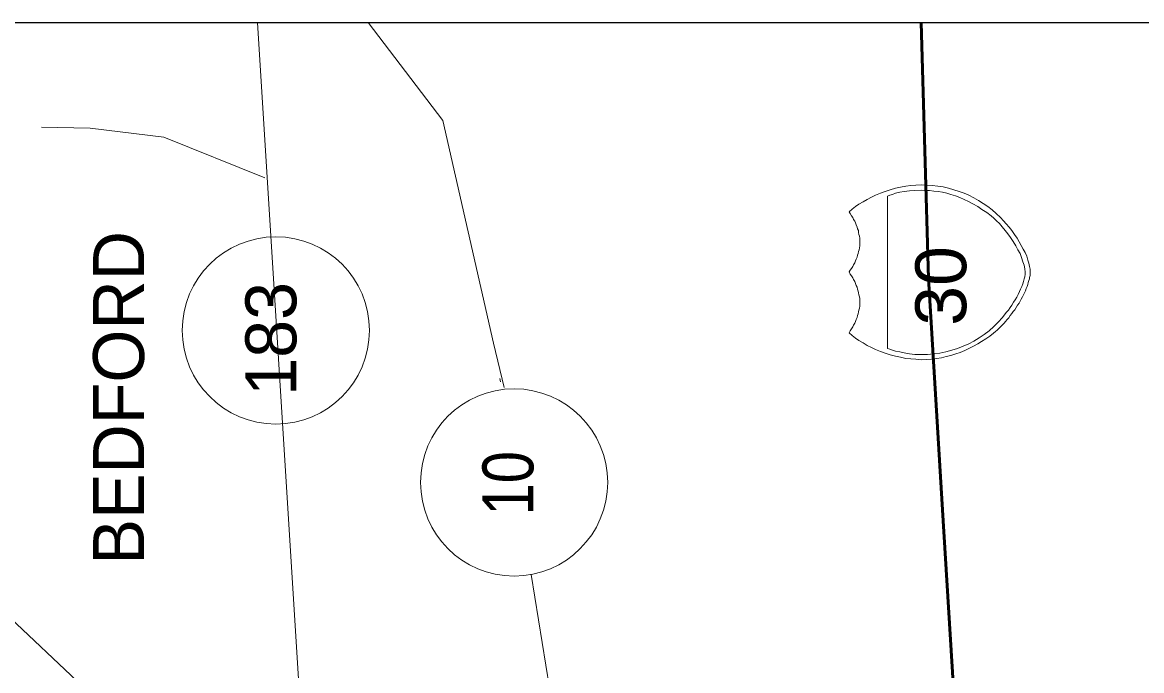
# Model space of a CAD drawing. Extents: x 2363323 to 2367082, y 6956018 to 6980837.
# Drawn here: x 2365426.8 to 2365762.8, y 6956343.7 to 6956538.2 of the extents above; entities that cross this region are included whole.
import ezdxf

# ---------------------------------------------------------------- set-up
doc = ezdxf.new("R2010")
doc.units = 0
doc.header["$LTSCALE"] = 4.1
for name, color, linetype, lineweight in [('61', 7, 'Continuous', 40), ('62', 7, 'Continuous', 13), ('63', 7, 'Continuous', 13)]:
    doc.layers.add(name, color=color, linetype=linetype, lineweight=lineweight)

msp = doc.modelspace()

# ---------------------------------------------------------------- linework, layer by layer
at = {"layer": '61', "lineweight": 25}
msp.add_lwpolyline([(2365293.134, 6956018.485), (2365293.134, 6956538.196), (2365958.89, 6956538.196), (2365958.89, 6956018.485)], close=True, dxfattribs=at)
at = {"layer": '62'}
for p, q in [((2365527.469, 6956056.34), (2365497.377, 6956538.196)), ((2365552.969, 6956508.784), (2365530.565, 6956538.196)), ((2365447.113, 6956506.444), (2365432.529, 6956506.716)), ((2365568.178, 6956441.987), (2365571.408, 6956428.587)), ((2365446.841, 6956337.136), (2365409.581, 6956372.152)), ((2365585.001, 6956338.484), (2365579.55, 6956372.48))]:
    msp.add_line(p, q, dxfattribs=at)
at = {"layer": '62', "lineweight": 53}
msp.add_line((2365708.857, 6956297.252), (2365703.273, 6956388.628), dxfattribs=at)
msp.add_lwpolyline([(2365696.665, 6956538.196), (2365698.781, 6956461.356), (2365703.273, 6956388.628)], dxfattribs=at)
at = {"layer": '62'}
for points in [[(2365499.593, 6956491.596), (2365469.265, 6956503.744), (2365447.113, 6956506.444)], [(2365676.336, 6956465.449), (2365676.675, 6956466.055), (2365676.945, 6956466.601), (2365677.149, 6956467.135), (2365677.416, 6956467.747), (2365677.485, 6956468.356), (2365677.755, 6956468.824), (2365677.827, 6956469.436), (2365677.959, 6956469.973), (2365678.091, 6956470.579), (2365678.157, 6956471.125), (2365678.157, 6956471.731), (2365678.157, 6956472.337), (2365678.157, 6956472.877), (2365678.157, 6956473.417), (2365678.091, 6956474.023), (2365677.956, 6956474.566), (2365677.827, 6956475.109), (2365677.758, 6956475.715), (2365677.488, 6956476.255), (2365677.419, 6956476.795), (2365677.146, 6956477.401), (2365676.945, 6956478.007), (2365676.675, 6956478.553), (2365676.339, 6956479.087), (2365676.069, 6956479.627), (2365675.727, 6956480.167), (2365675.319, 6956480.845), (2365674.986, 6956481.379), (2365675.868, 6956482.126), (2365676.876, 6956482.939), (2365677.953, 6956483.677), (2365679.171, 6956484.355), (2365680.386, 6956485.027), (2365681.673, 6956485.771), (2365682.951, 6956486.377), (2365684.373, 6956486.986), (2365685.855, 6956487.463), (2365687.337, 6956487.931), (2365688.891, 6956488.405), (2365690.448, 6956488.741), (2365691.999, 6956489.017), (2365693.487, 6956489.209), (2365695.035, 6956489.353), (2365696.586, 6956489.419), (2365698.275, 6956489.347), (2365699.967, 6956489.215), (2365701.647, 6956489.017), (2365703.201, 6956488.807), (2365704.821, 6956488.471), (2365706.447, 6956487.931), (2365707.995, 6956487.457), (2365709.549, 6956486.986), (2365710.965, 6956486.311), (2365712.447, 6956485.507), (2365713.866, 6956484.757), (2365715.219, 6956483.881), (2365716.635, 6956482.936), (2365717.916, 6956481.925), (2365719.131, 6956480.845), (2365720.415, 6956479.627), (2365721.297, 6956478.685), (2365722.167, 6956477.737), (2365723.049, 6956476.726), (2365723.859, 6956475.715), (2365724.597, 6956474.566), (2365725.407, 6956473.417), (2365726.085, 6956472.337), (2365726.691, 6956471.257), (2365727.297, 6956470.183), (2365727.837, 6956469.097), (2365728.311, 6956468.017), (2365728.647, 6956466.865), (2365728.923, 6956465.989), (2365729.121, 6956464.975), (2365729.325, 6956464.099), (2365729.325, 6956463.283)], [(2365729.325, 6956463.283), (2365729.325, 6956462.749), (2365729.325, 6956462.275), (2365729.187, 6956461.675), (2365729.121, 6956461.195), (2365728.986, 6956460.724), (2365728.788, 6956460.112), (2365728.647, 6956459.509), (2365728.446, 6956458.903), (2365728.176, 6956458.294), (2365727.906, 6956457.685), (2365727.639, 6956457.013), (2365727.366, 6956456.473), (2365727.027, 6956455.795), (2365726.691, 6956455.183), (2365726.355, 6956454.583), (2365726.019, 6956453.905), (2365725.545, 6956453.299), (2365725.137, 6956452.621), (2365724.735, 6956451.949), (2365724.267, 6956451.403), (2365723.859, 6956450.797), (2365723.319, 6956450.194), (2365722.917, 6956449.519), (2365722.437, 6956449.045), (2365721.966, 6956448.439), (2365721.495, 6956447.893), (2365720.955, 6956447.293), (2365720.418, 6956446.825), (2365719.878, 6956446.279), (2365719.401, 6956445.805), (2365718.927, 6956445.406), (2365718.321, 6956444.923), (2365717.241, 6956444.053), (2365716.029, 6956443.243), (2365714.748, 6956442.436), (2365713.596, 6956441.752), (2365712.315, 6956441.011), (2365710.965, 6956440.339), (2365709.687, 6956439.727), (2365708.331, 6956439.187), (2365706.987, 6956438.713), (2365705.565, 6956438.242), (2365704.149, 6956437.903), (2365702.727, 6956437.567), (2365701.248, 6956437.297), (2365699.763, 6956437.162), (2365698.143, 6956437.021), (2365696.586, 6956436.961), (2365695.035, 6956437.093), (2365693.481, 6956437.231), (2365691.999, 6956437.369), (2365690.445, 6956437.702), (2365688.891, 6956438.044), (2365687.343, 6956438.443), (2365685.855, 6956438.917), (2365684.373, 6956439.391), (2365682.951, 6956439.997), (2365681.673, 6956440.6), (2365680.386, 6956441.281), (2365679.171, 6956442.025), (2365677.956, 6956442.763), (2365676.876, 6956443.444), (2365675.868, 6956444.254), (2365674.989, 6956445.001), (2365675.325, 6956445.604), (2365675.727, 6956446.216), (2365676.069, 6956446.819), (2365676.336, 6956447.296), (2365676.678, 6956447.899), (2365676.948, 6956448.439), (2365677.146, 6956449.045), (2365677.416, 6956449.654), (2365677.488, 6956450.194), (2365677.755, 6956450.734), (2365677.821, 6956451.346), (2365677.956, 6956451.883), (2365678.091, 6956452.483), (2365678.157, 6956453.029), (2365678.157, 6956453.575), (2365678.163, 6956454.244), (2365678.157, 6956454.715), (2365678.163, 6956455.324), (2365678.097, 6956455.867), (2365677.956, 6956456.473), (2365677.827, 6956457.016), (2365677.755, 6956457.556), (2365677.488, 6956458.165), (2365677.416, 6956458.765), (2365677.146, 6956459.239), (2365676.948, 6956459.851), (2365676.678, 6956460.454), (2365676.336, 6956461.066), (2365676.066, 6956461.534), (2365675.733, 6956462.143), (2365675.328, 6956462.683), (2365674.986, 6956463.295), (2365675.325, 6956463.829), (2365675.733, 6956464.297), (2365676.066, 6956464.915), (2365676.336, 6956465.449)]]:
    msp.add_lwpolyline(points, dxfattribs=at)
msp.add_lwpolyline([(2365686.533, 6956486.041), (2365686.527, 6956440.339), (2365687.208, 6956440.132), (2365688.015, 6956439.793), (2365688.957, 6956439.523), (2365690.241, 6956439.325), (2365691.525, 6956438.989), (2365693.076, 6956438.719), (2365694.765, 6956438.581), (2365696.589, 6956438.512), (2365698.479, 6956438.581), (2365700.366, 6956438.713), (2365702.256, 6956438.983), (2365704.011, 6956439.322), (2365705.835, 6956439.793), (2365707.521, 6956440.333), (2365709.276, 6956441.011), (2365710.896, 6956441.752), (2365712.447, 6956442.571), (2365714.073, 6956443.516), (2365715.558, 6956444.524), (2365717.037, 6956445.676), (2365718.459, 6956446.954), (2365719.737, 6956448.235), (2365721.021, 6956449.654), (2365722.173, 6956451.139), (2365722.845, 6956451.814), (2365723.319, 6956452.621), (2365723.856, 6956453.365), (2365724.327, 6956454.244), (2365724.807, 6956454.919), (2365725.341, 6956455.729), (2365725.746, 6956456.545), (2365726.151, 6956457.415), (2365726.487, 6956458.159), (2365726.826, 6956458.969), (2365727.165, 6956459.785), (2365727.369, 6956460.454), (2365727.567, 6956461.195), (2365727.708, 6956461.873), (2365727.837, 6956462.614), (2365727.843, 6956463.289), (2365727.771, 6956464.234), (2365727.567, 6956465.383), (2365727.165, 6956466.394), (2365726.757, 6956467.675), (2365726.355, 6956468.833), (2365725.677, 6956469.976), (2365725.005, 6956471.191), (2365724.267, 6956472.406), (2365723.451, 6956473.621), (2365722.641, 6956474.707), (2365721.831, 6956475.781), (2365720.958, 6956476.861), (2365720.148, 6956477.875), (2365719.266, 6956478.685), (2365718.459, 6956479.498), (2365717.646, 6956480.101), (2365716.296, 6956481.115), (2365714.877, 6956482.057), (2365713.596, 6956482.936), (2365712.111, 6956483.746), (2365710.827, 6956484.421), (2365709.546, 6956485.027), (2365708.265, 6956485.639), (2365706.915, 6956486.107), (2365705.559, 6956486.581), (2365704.344, 6956486.986), (2365702.997, 6956487.256), (2365701.719, 6956487.457), (2365700.438, 6956487.595), (2365699.151, 6956487.796), (2365697.873, 6956487.796), (2365696.589, 6956487.865), (2365694.765, 6956487.796), (2365693.076, 6956487.667), (2365691.525, 6956487.457), (2365690.241, 6956487.256), (2365688.963, 6956486.917), (2365688.015, 6956486.581), (2365687.208, 6956486.311)], close=True, dxfattribs=at)
for centre in [(2365502.86, 6956445.764), (2365574.403, 6956400.15)]:
    msp.add_circle(centre, 28.094, dxfattribs=at)
at = {"layer": '63'}
for p, q in [((2365447.113, 6956506.444), (2365432.529, 6956506.716)), ((2365570.278, 6956430.305), (2365570.14, 6956431.316)), ((2365446.841, 6956337.136), (2365409.581, 6956372.152))]:
    msp.add_line(p, q, dxfattribs=at)
at = {"layer": '63', "lineweight": 53}
msp.add_line((2365708.857, 6956297.252), (2365703.273, 6956388.628), dxfattribs=at)
at = {"layer": '63'}
for points in [[(2365568.178, 6956441.987), (2365552.969, 6956508.784), (2365530.565, 6956538.196)], [(2365499.593, 6956491.596), (2365469.265, 6956503.744), (2365447.113, 6956506.444)], [(2365676.336, 6956465.449), (2365676.675, 6956466.055), (2365676.945, 6956466.601), (2365677.149, 6956467.135), (2365677.416, 6956467.747), (2365677.485, 6956468.356), (2365677.755, 6956468.824), (2365677.827, 6956469.436), (2365677.959, 6956469.973), (2365678.091, 6956470.579), (2365678.157, 6956471.125), (2365678.157, 6956471.731), (2365678.157, 6956472.337), (2365678.157, 6956472.877), (2365678.157, 6956473.417), (2365678.091, 6956474.023), (2365677.956, 6956474.566), (2365677.827, 6956475.109), (2365677.758, 6956475.715), (2365677.488, 6956476.255), (2365677.419, 6956476.795), (2365677.146, 6956477.401), (2365676.945, 6956478.007), (2365676.675, 6956478.553), (2365676.339, 6956479.087), (2365676.069, 6956479.627), (2365675.727, 6956480.167), (2365675.319, 6956480.845), (2365674.986, 6956481.379), (2365675.868, 6956482.126), (2365676.876, 6956482.939), (2365677.953, 6956483.677), (2365679.171, 6956484.355), (2365680.386, 6956485.027), (2365681.673, 6956485.771), (2365682.951, 6956486.377), (2365684.373, 6956486.986), (2365685.855, 6956487.463), (2365687.337, 6956487.931), (2365688.891, 6956488.405), (2365690.448, 6956488.741), (2365691.999, 6956489.017), (2365693.487, 6956489.209), (2365695.035, 6956489.353), (2365696.586, 6956489.419), (2365698.275, 6956489.347), (2365699.967, 6956489.215), (2365701.647, 6956489.017), (2365703.201, 6956488.807), (2365704.821, 6956488.471), (2365706.447, 6956487.931), (2365707.995, 6956487.457), (2365709.549, 6956486.986), (2365710.965, 6956486.311), (2365712.447, 6956485.507), (2365713.866, 6956484.757), (2365715.219, 6956483.881), (2365716.635, 6956482.936), (2365717.916, 6956481.925), (2365719.131, 6956480.845), (2365720.415, 6956479.627), (2365721.297, 6956478.685), (2365722.167, 6956477.737), (2365723.049, 6956476.726), (2365723.859, 6956475.715), (2365724.597, 6956474.566), (2365725.407, 6956473.417), (2365726.085, 6956472.337), (2365726.691, 6956471.257), (2365727.297, 6956470.183), (2365727.837, 6956469.097), (2365728.311, 6956468.017), (2365728.647, 6956466.865), (2365728.923, 6956465.989), (2365729.121, 6956464.975), (2365729.325, 6956464.099), (2365729.325, 6956463.283)], [(2365729.325, 6956463.283), (2365729.325, 6956462.749), (2365729.325, 6956462.275), (2365729.187, 6956461.675), (2365729.121, 6956461.195), (2365728.986, 6956460.724), (2365728.788, 6956460.112), (2365728.647, 6956459.509), (2365728.446, 6956458.903), (2365728.176, 6956458.294), (2365727.906, 6956457.685), (2365727.639, 6956457.013), (2365727.366, 6956456.473), (2365727.027, 6956455.795), (2365726.691, 6956455.183), (2365726.355, 6956454.583), (2365726.019, 6956453.905), (2365725.545, 6956453.299), (2365725.137, 6956452.621), (2365724.735, 6956451.949), (2365724.267, 6956451.403), (2365723.859, 6956450.797), (2365723.319, 6956450.194), (2365722.917, 6956449.519), (2365722.437, 6956449.045), (2365721.966, 6956448.439), (2365721.495, 6956447.893), (2365720.955, 6956447.293), (2365720.418, 6956446.825), (2365719.878, 6956446.279), (2365719.401, 6956445.805), (2365718.927, 6956445.406), (2365718.321, 6956444.923), (2365717.241, 6956444.053), (2365716.029, 6956443.243), (2365714.748, 6956442.436), (2365713.596, 6956441.752), (2365712.315, 6956441.011), (2365710.965, 6956440.339), (2365709.687, 6956439.727), (2365708.331, 6956439.187), (2365706.987, 6956438.713), (2365705.565, 6956438.242), (2365704.149, 6956437.903), (2365702.727, 6956437.567), (2365701.248, 6956437.297), (2365699.763, 6956437.162), (2365698.143, 6956437.021), (2365696.586, 6956436.961), (2365695.035, 6956437.093), (2365693.481, 6956437.231), (2365691.999, 6956437.369), (2365690.445, 6956437.702), (2365688.891, 6956438.044), (2365687.343, 6956438.443), (2365685.855, 6956438.917), (2365684.373, 6956439.391), (2365682.951, 6956439.997), (2365681.673, 6956440.6), (2365680.386, 6956441.281), (2365679.171, 6956442.025), (2365677.956, 6956442.763), (2365676.876, 6956443.444), (2365675.868, 6956444.254), (2365674.989, 6956445.001), (2365675.325, 6956445.604), (2365675.727, 6956446.216), (2365676.069, 6956446.819), (2365676.336, 6956447.296), (2365676.678, 6956447.899), (2365676.948, 6956448.439), (2365677.146, 6956449.045), (2365677.416, 6956449.654), (2365677.488, 6956450.194), (2365677.755, 6956450.734), (2365677.821, 6956451.346), (2365677.956, 6956451.883), (2365678.091, 6956452.483), (2365678.157, 6956453.029), (2365678.157, 6956453.575), (2365678.163, 6956454.244), (2365678.157, 6956454.715), (2365678.163, 6956455.324), (2365678.097, 6956455.867), (2365677.956, 6956456.473), (2365677.827, 6956457.016), (2365677.755, 6956457.556), (2365677.488, 6956458.165), (2365677.416, 6956458.765), (2365677.146, 6956459.239), (2365676.948, 6956459.851), (2365676.678, 6956460.454), (2365676.336, 6956461.066), (2365676.066, 6956461.534), (2365675.733, 6956462.143), (2365675.328, 6956462.683), (2365674.986, 6956463.295), (2365675.325, 6956463.829), (2365675.733, 6956464.297), (2365676.066, 6956464.915), (2365676.336, 6956465.449)]]:
    msp.add_lwpolyline(points, dxfattribs=at)
at = {"layer": '63', "lineweight": 53}
msp.add_lwpolyline([(2365696.665, 6956538.196), (2365698.781, 6956461.356), (2365703.273, 6956388.628)], dxfattribs=at)
at = {"layer": '63'}
msp.add_lwpolyline([(2365686.533, 6956486.041), (2365686.527, 6956440.339), (2365687.208, 6956440.132), (2365688.015, 6956439.793), (2365688.957, 6956439.523), (2365690.241, 6956439.325), (2365691.525, 6956438.989), (2365693.076, 6956438.719), (2365694.765, 6956438.581), (2365696.589, 6956438.512), (2365698.479, 6956438.581), (2365700.366, 6956438.713), (2365702.256, 6956438.983), (2365704.011, 6956439.322), (2365705.835, 6956439.793), (2365707.521, 6956440.333), (2365709.276, 6956441.011), (2365710.896, 6956441.752), (2365712.447, 6956442.571), (2365714.073, 6956443.516), (2365715.558, 6956444.524), (2365717.037, 6956445.676), (2365718.459, 6956446.954), (2365719.737, 6956448.235), (2365721.021, 6956449.654), (2365722.173, 6956451.139), (2365722.845, 6956451.814), (2365723.319, 6956452.621), (2365723.856, 6956453.365), (2365724.327, 6956454.244), (2365724.807, 6956454.919), (2365725.341, 6956455.729), (2365725.746, 6956456.545), (2365726.151, 6956457.415), (2365726.487, 6956458.159), (2365726.826, 6956458.969), (2365727.165, 6956459.785), (2365727.369, 6956460.454), (2365727.567, 6956461.195), (2365727.708, 6956461.873), (2365727.837, 6956462.614), (2365727.843, 6956463.289), (2365727.771, 6956464.234), (2365727.567, 6956465.383), (2365727.165, 6956466.394), (2365726.757, 6956467.675), (2365726.355, 6956468.833), (2365725.677, 6956469.976), (2365725.005, 6956471.191), (2365724.267, 6956472.406), (2365723.451, 6956473.621), (2365722.641, 6956474.707), (2365721.831, 6956475.781), (2365720.958, 6956476.861), (2365720.148, 6956477.875), (2365719.266, 6956478.685), (2365718.459, 6956479.498), (2365717.646, 6956480.101), (2365716.296, 6956481.115), (2365714.877, 6956482.057), (2365713.596, 6956482.936), (2365712.111, 6956483.746), (2365710.827, 6956484.421), (2365709.546, 6956485.027), (2365708.265, 6956485.639), (2365706.915, 6956486.107), (2365705.559, 6956486.581), (2365704.344, 6956486.986), (2365702.997, 6956487.256), (2365701.719, 6956487.457), (2365700.438, 6956487.595), (2365699.151, 6956487.796), (2365697.873, 6956487.796), (2365696.589, 6956487.865), (2365694.765, 6956487.796), (2365693.076, 6956487.667), (2365691.525, 6956487.457), (2365690.241, 6956487.256), (2365688.963, 6956486.917), (2365688.015, 6956486.581), (2365687.208, 6956486.311)], close=True, dxfattribs=at)
for centre in [(2365502.86, 6956445.764), (2365574.403, 6956400.15)]:
    msp.add_circle(centre, 28.094, dxfattribs=at)

# ---------------------------------------------------------------- texts
at = {"layer": '62'}
for s, p in [('BEDFORD', (2365463.283, 6956375.532)), ('183', (2365509.013, 6956426.166))]:
    msp.add_text(s, height=15.3, rotation=90, dxfattribs=at).set_placement(p)
for s, width, p in [('30', 1.05, (2365710.155, 6956447.161)), ('10', 0.85, (2365580.193, 6956390.222))]:
    msp.add_text(s, height=15.3, rotation=90, dxfattribs=dict(at, width=width)).set_placement(p)

doc.saveas('drawing.dxf')
